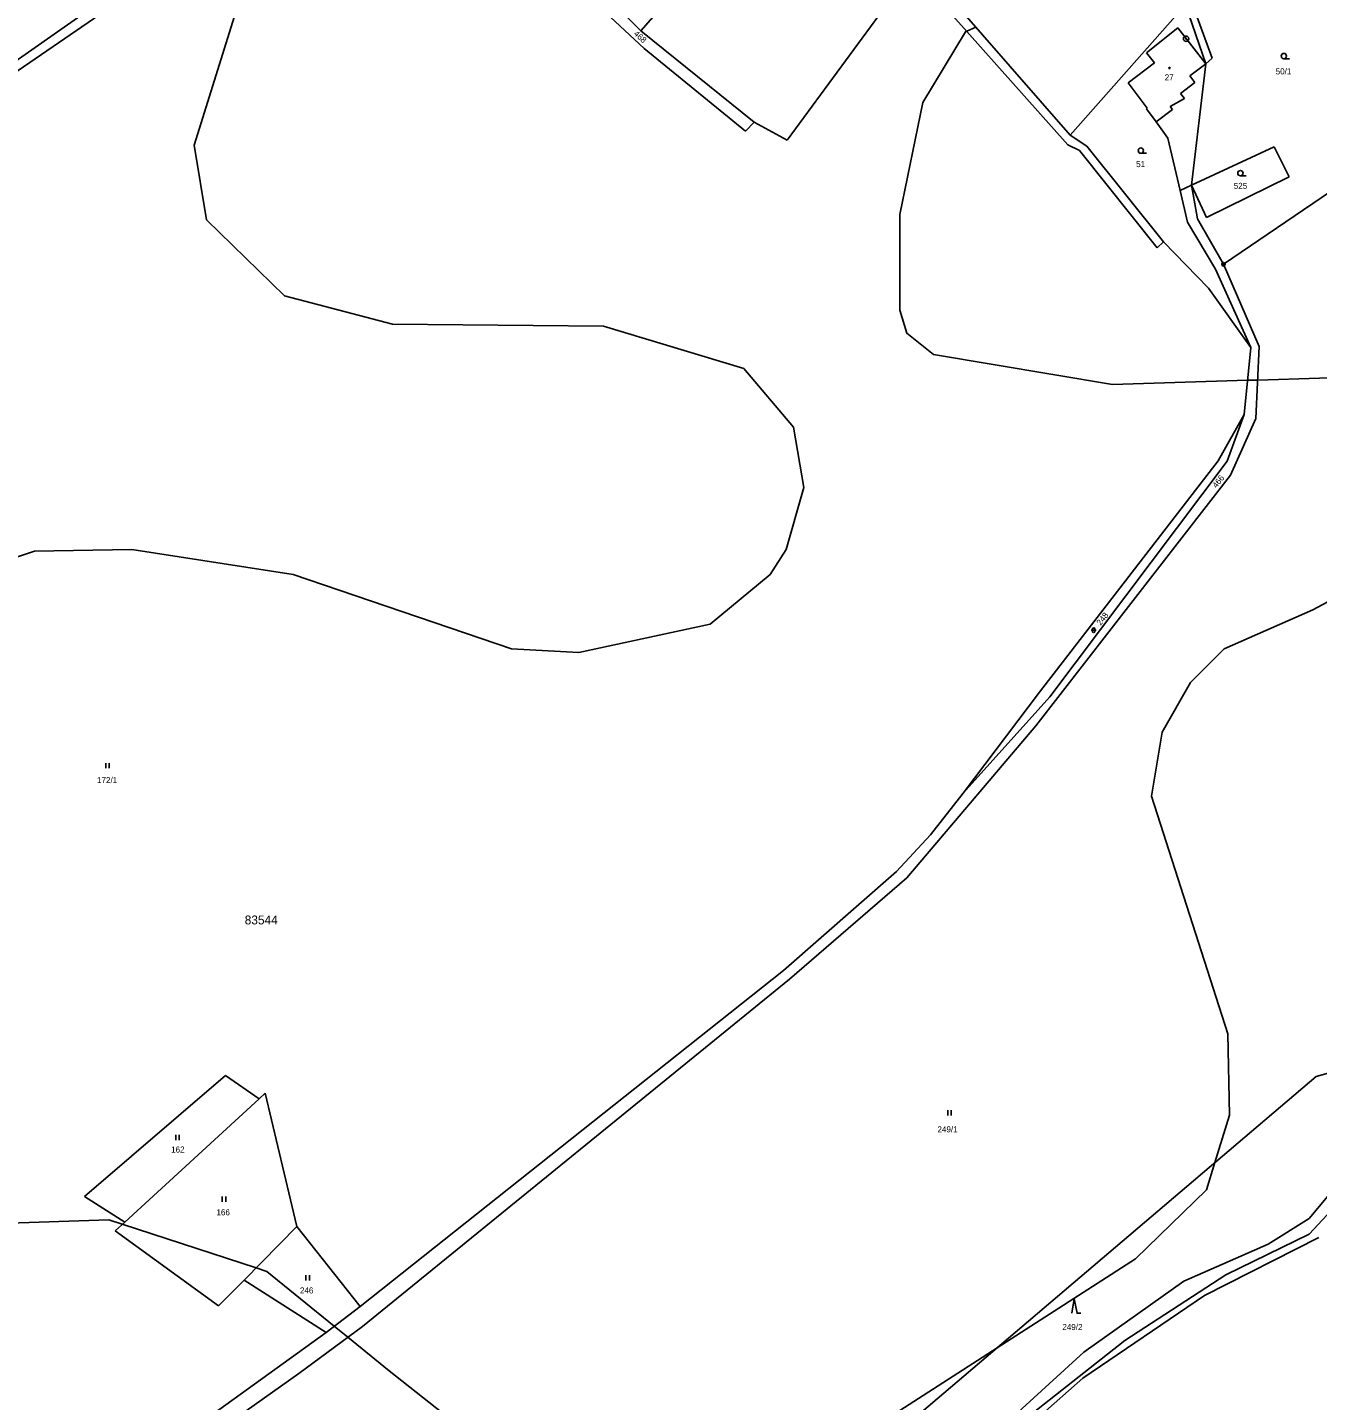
# Model space of a CAD drawing. Extents: x -547623 to -538651, y -1096714 to -1086522.
# Drawn here: x -543976.5 to -543612.7, y -1094983.9 to -1094596.8 of the extents above; entities that cross this region are included whole.
import ezdxf

# ---------------------------------------------------------------- set-up
doc = ezdxf.new("R2010")
doc.units = 0
for name, color, linetype in [('podzemní_provozovana', 7, 'Continuous'), ('Vrstva 1', 7, 'Continuous'), ('Vrstva 25', 7, 'Continuous'), ('Vrstva 33', 7, 'Continuous'), ('Vrstva 52', 7, 'Continuous'), ('Vrstva 53', 7, 'Continuous'), ('Vrstva 83', 7, 'Continuous'), ('Vrstva 86', 7, 'Continuous'), ('Vrstva 90', 7, 'Continuous'), ('Vrstva 92', 7, 'Continuous')]:
    doc.layers.add(name, color=color, linetype=linetype)

msp = doc.modelspace()

# ---------------------------------------------------------------- linework, layer by layer
at = {"layer": 'Vrstva 1'}
for points in [[(-543760.02, -1094548.17), (-543803.48, -1094597.8)], [(-543982.35, -1094611.21), (-543913.61, -1094563.96)], [(-543833.89, -1094567.38), (-543803.48, -1094597.8)], [(-543983.7, -1094609), (-543939.12, -1094577.76)], [(-543827.12, -1094579.85), (-543802.53, -1094602.76)], [(-543762.22, -1094628.56), (-543726.99, -1094580.55)], [(-543726.99, -1094580.55), (-543683.14, -1094629.86)], [(-543724.08, -1094579.41), (-543682.46, -1094627.2)], [(-543642.38, -1094605.45), (-543648.35, -1094589.34)], [(-543682.46, -1094627.2), (-543649.91, -1094590.44)], [(-543644.2, -1094607.09), (-543649.91, -1094590.44)], [(-543652.06, -1094596.93), (-543660.89, -1094603.94)], [(-543652.06, -1094596.93), (-543644.2, -1094607.09)], [(-543803.48, -1094597.8), (-543771.54, -1094623.54)], [(-543802.53, -1094602.76), (-543774.01, -1094626.07)], [(-543660.89, -1094603.94), (-543658.64, -1094606.75)], [(-543658.64, -1094606.75), (-543666.06, -1094612.41)], [(-543648.24, -1094641.31), (-543644.2, -1094607.09)], [(-543644.2, -1094607.09), (-543642.38, -1094605.45)], [(-543666.06, -1094612.41), (-543660.7, -1094619.58)], [(-543660.94, -1094619.76), (-543660.7, -1094619.58)], [(-543658.22, -1094623.37), (-543660.94, -1094619.76)], [(-543774.01, -1094626.07), (-543771.54, -1094623.54)], [(-543771.54, -1094623.54), (-543762.22, -1094628.56)], [(-543654.91, -1094628.01), (-543658.22, -1094623.37)], [(-543677.7, -1094630.27), (-543682.46, -1094627.2)], [(-543651.44, -1094642.8), (-543654.91, -1094628.01)], [(-543683.14, -1094629.86), (-543679.83, -1094631.49)], [(-543679.83, -1094631.49), (-543657.95, -1094658.94)], [(-543656.08, -1094657.22), (-543677.7, -1094630.27)], [(-543624.92, -1094630.42), (-543648.24, -1094641.31)], [(-543620.72, -1094638.88), (-543624.92, -1094630.42)], [(-543643.98, -1094650.42), (-543620.72, -1094638.88)], [(-543648.24, -1094641.31), (-543651.44, -1094642.8)], [(-543649.36, -1094651.67), (-543651.44, -1094642.8)], [(-543646.55, -1094650.76), (-543648.24, -1094641.31)], [(-543648.24, -1094641.31), (-543643.98, -1094650.42)], [(-543639.2, -1094663.57), (-543609.01, -1094643.02)], [(-543639.2, -1094663.57), (-543646.55, -1094650.76)], [(-543641.46, -1094664.98), (-543649.36, -1094651.67)], [(-543657.95, -1094658.94), (-543656.08, -1094657.22)], [(-543656.08, -1094657.22), (-543643.44, -1094670.29)], [(-543631.48, -1094687.01), (-543641.46, -1094664.98)], [(-543629.1, -1094686.75), (-543639.2, -1094663.57)], [(-543643.44, -1094670.29), (-543631.48, -1094687.01)], [(-543633.35, -1094705.93), (-543631.48, -1094687.01)], [(-543630.08, -1094707.08), (-543629.1, -1094686.75)], [(-543633.35, -1094705.93), (-543640.68, -1094719.02)], [(-543638.12, -1094719.05), (-543633.35, -1094705.93)], [(-543637.27, -1094723.03), (-543630.08, -1094707.08)], [(-543640.68, -1094719.02), (-543691.05, -1094784.18)], [(-543688.17, -1094785.5), (-543638.12, -1094719.05)], [(-543692.16, -1094793.74), (-543637.27, -1094723.03)], [(-543691.05, -1094784.18), (-543712.63, -1094812.72)], [(-543712.63, -1094812.72), (-543688.17, -1094785.5)], [(-543728.48, -1094836.56), (-543692.16, -1094793.74)], [(-543721.87, -1094824.39), (-543712.63, -1094812.72)], [(-543731.44, -1094834.75), (-543721.87, -1094824.39)], [(-543763.23, -1094862.64), (-543731.44, -1094834.75)], [(-543761.55, -1094865.14), (-543728.48, -1094836.56)], [(-543882.69, -1094957.37), (-543763.23, -1094862.64)], [(-543882.01, -1094963.04), (-543761.55, -1094865.14)], [(-543613.04, -1094892.52), (-543591.14, -1094886.44)], [(-543960.37, -1094926.42), (-543920.65, -1094892.3)], [(-543920.65, -1094892.3), (-543911.17, -1094898.9)], [(-543744.43, -1095004.33), (-543613.04, -1094892.52)], [(-543949.03, -1094933.6), (-543911.17, -1094898.9)], [(-543911.17, -1094898.9), (-543909.41, -1094897.29)], [(-543909.41, -1094897.29), (-543900.48, -1094934.89)], [(-543615.01, -1094932.55), (-543596.64, -1094910.53)], [(-543949.03, -1094933.6), (-543960.37, -1094926.42)], [(-543951.74, -1094936.08), (-543949.03, -1094933.6)], [(-543626.58, -1094939.83), (-543615.01, -1094932.55)], [(-543922.6, -1094957.2), (-543951.74, -1094936.08)], [(-543900.48, -1094934.89), (-543915.4, -1094949.94)], [(-543900.48, -1094934.89), (-543882.69, -1094957.37)], [(-543650.35, -1094950.3), (-543626.58, -1094939.83)], [(-543612.32, -1094937.96), (-543644.56, -1094954.33)], [(-543915.4, -1094949.94), (-543922.6, -1094957.2)], [(-543892.21, -1094964.69), (-543915.4, -1094949.94)], [(-543678.62, -1094970.27), (-543650.35, -1094950.3)], [(-543644.56, -1094954.33), (-543678.87, -1094977.62)], [(-543882.69, -1094957.37), (-543892.21, -1094964.69)], [(-543892.21, -1094964.69), (-543954.54, -1095009.68)], [(-543899.96, -1094976.33), (-543882.01, -1094963.04)], [(-543698.12, -1094988.11), (-543678.62, -1094970.27)], [(-543949.67, -1095011.52), (-543899.96, -1094976.33)], [(-543678.87, -1094977.62), (-543695.06, -1094991.9)]]:
    msp.add_lwpolyline(points, dxfattribs=at)
at = {"layer": 'Vrstva 25'}
for p, q in [((-543622.19, -1094605.63), (-543620.59, -1094605.63)), ((-543662.51, -1094632.26), (-543660.91, -1094632.26)), ((-543634.42, -1094638.63), (-543632.82, -1094638.63)), ((-543676.47, -1094766.74), (-543675.13, -1094766.74)), ((-543676.14, -1094767.07), (-543676.14, -1094766.41)), ((-543675.46, -1094766.41), (-543675.46, -1094767.07)), ((-543954.41, -1094805.68), (-543954.41, -1094804.18)), ((-543953.41, -1094805.68), (-543953.41, -1094804.18)), ((-543716.97, -1094903.53), (-543716.97, -1094902.03)), ((-543715.97, -1094903.53), (-543715.97, -1094902.03)), ((-543934.65, -1094910.48), (-543934.65, -1094908.98)), ((-543933.65, -1094910.48), (-543933.65, -1094908.98)), ((-543921.56, -1094927.91), (-543921.56, -1094926.41)), ((-543920.56, -1094927.91), (-543920.56, -1094926.41)), ((-543897.93, -1094950.07), (-543897.93, -1094948.57)), ((-543896.93, -1094950.07), (-543896.93, -1094948.57))]:
    msp.add_line(p, q, dxfattribs=at)
msp.add_lwpolyline([(-543681.97, -1094959.29), (-543681.27, -1094955.29), (-543680.47, -1094959.29), (-543679.47, -1094959.29)], dxfattribs=at)
for centre, radius in [((-543622.19, -1094604.88), 0.75), ((-543654.44, -1094608.26), 0.175), ((-543662.51, -1094631.51), 0.75), ((-543634.42, -1094637.88), 0.75)]:
    msp.add_circle(centre, radius, dxfattribs=at)
for centre, start, end in [((-543675.8, -1094766.41), 0, 180), ((-543675.8, -1094767.07), 180, 0)]:
    msp.add_arc(centre, 0.335, start, end, dxfattribs=at)
at = {"layer": 'Vrstva 33'}
for points in [[(-543644.2, -1094607.09), (-543648.67, -1094610.47)], [(-543647.27, -1094612.3), (-543651.29, -1094615.38)], [(-543648.67, -1094610.47), (-543647.27, -1094612.3)], [(-543651.29, -1094615.38), (-543650.2, -1094616.8)], [(-543653.55, -1094619.96), (-543658.22, -1094623.37)], [(-543650.2, -1094616.8), (-543654.21, -1094619.09)], [(-543654.21, -1094619.09), (-543653.55, -1094619.96)]]:
    msp.add_lwpolyline(points, dxfattribs=at)
at = {"layer": 'Vrstva 52'}
for points in [[(-543911, -1094571), (-543929.5, -1094630), (-543926, -1094651), (-543904, -1094672.5), (-543873.5, -1094680.5), (-543814, -1094681), (-543774.5, -1094693), (-543760.5, -1094709.5), (-543757.5, -1094726.5), (-543762.5, -1094744), (-543767, -1094751), (-543784, -1094765), (-543821, -1094773), (-543840, -1094772), (-543901.5, -1094751), (-543947, -1094744), (-543974.5, -1094744.5), (-544015.5, -1094758)], [(-543709.01, -1094596.72), (-543711.62, -1094597.84), (-543712, -1094598), (-543724, -1094618), (-543730.5, -1094649.5), (-543730.5, -1094676.5), (-543728.5, -1094683), (-543721, -1094689), (-543670.5, -1094697.5), (-543632.4, -1094696.29), (-543629.56, -1094696.2), (-543560, -1094694)], [(-543719, -1095008), (-543667, -1094967), (-543638.5, -1094948.5), (-543615, -1094937), (-543593.71, -1094914.1), (-543588.5, -1094908.5), (-543568, -1094836.5), (-543543.32, -1094786.45), (-543532.84, -1094765.19), (-543532.5, -1094764.5), (-543490.5, -1094691), (-543534.52, -1094653.52), (-543541, -1094648), (-543495.68, -1094647.31), (-543483.43, -1094647.12), (-543479.29, -1094647.06), (-543475.5, -1094647), (-543477.5, -1094640), (-543493, -1094642), (-543493.36, -1094627.42), (-543493.5, -1094621.5)], [(-543541, -1094722), (-543614, -1094761), (-543639, -1094772), (-543648.5, -1094781.5), (-543656.5, -1094795.5), (-543659.5, -1094813.5), (-543638, -1094880.5), (-543637.5, -1094903.5), (-543641.63, -1094916.85), (-543644, -1094924.5), (-543664, -1094944), (-543702.99, -1094969.06), (-543750, -1094999.29)], [(-543827, -1095013), (-543874.5, -1094975.5), (-543886.11, -1094966.08), (-543889.96, -1094962.96), (-543909, -1094947.5), (-543912.01, -1094946.52), (-543949.72, -1094934.23), (-543953.5, -1094933), (-543984.5, -1094934), (-544003, -1094942.5), (-544030.47, -1094966.05), (-544031, -1094966.5), (-544102, -1095038.5)]]:
    msp.add_lwpolyline(points, dxfattribs=at)
at = {"layer": 'Vrstva 83'}
for centre, radius in [((-543649.76, -1094599.97), 0.75), ((-543649.76, -1094599.97), 0.1), ((-543639.2, -1094663.57), 0.5), ((-543639.2, -1094663.57), 0.1)]:
    msp.add_circle(centre, radius, dxfattribs=at)
at = {"layer": 'Vrstva 90'}
for points in [[(-543652.06, -1094596.93), (-543660.89, -1094603.94)], [(-543652.06, -1094596.93), (-543644.2, -1094607.09)], [(-543660.89, -1094603.94), (-543658.64, -1094606.75)], [(-543658.64, -1094606.75), (-543666.06, -1094612.41)], [(-543644.2, -1094607.09), (-543648.67, -1094610.47)], [(-543666.06, -1094612.41), (-543660.7, -1094619.58)], [(-543647.27, -1094612.3), (-543651.29, -1094615.38)], [(-543648.67, -1094610.47), (-543647.27, -1094612.3)], [(-543651.29, -1094615.38), (-543650.2, -1094616.8)], [(-543660.94, -1094619.76), (-543660.7, -1094619.58)], [(-543658.22, -1094623.37), (-543660.94, -1094619.76)], [(-543653.55, -1094619.96), (-543658.22, -1094623.37)], [(-543650.2, -1094616.8), (-543654.21, -1094619.09)], [(-543654.21, -1094619.09), (-543653.55, -1094619.96)]]:
    msp.add_lwpolyline(points, dxfattribs=at)

# ---------------------------------------------------------------- texts
at = {"layer": 'podzemní_provozovana'}
msp.add_text('466', height=1.7, rotation=51.9283, dxfattribs=at).set_placement((-543641.17, -1094726.81))
at = {"layer": 'Vrstva 53'}
msp.add_text('83544', height=2.5, dxfattribs=at).set_placement((-543915.2, -1094849.68))
at = {"layer": 'Vrstva 86'}
for s, rotation, p in [('468', 317.2229, (-543805.64, -1094598.77)), ('248', 51.2892, (-543673.86, -1094765.54))]:
    msp.add_text(s, height=1.7, rotation=rotation, dxfattribs=at).set_placement(p)
for s, p in [('50/1', (-543624.49, -1094610.04)), ('51', (-543663.83, -1094636.18)), ('525', (-543636.32, -1094642.32)), ('172/1', (-543956.85, -1094809.85)), ('249/1', (-543719.86, -1094908.3)), ('162', (-543935.96, -1094914)), ('166', (-543923.18, -1094931.69)), ('246', (-543899.64, -1094953.72)), ('249/2', (-543684.65, -1094964.03))]:
    msp.add_text(s, height=1.7, dxfattribs=at).set_placement(p)
at = {"layer": 'Vrstva 92'}
msp.add_text('27', height=1.7, dxfattribs=at).set_placement((-543655.78, -1094611.73))

doc.saveas('drawing.dxf')
